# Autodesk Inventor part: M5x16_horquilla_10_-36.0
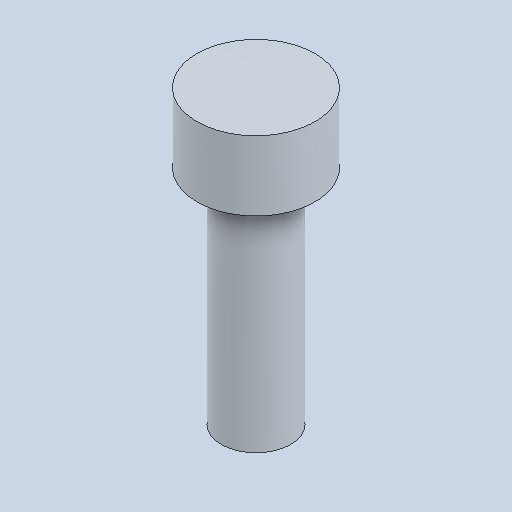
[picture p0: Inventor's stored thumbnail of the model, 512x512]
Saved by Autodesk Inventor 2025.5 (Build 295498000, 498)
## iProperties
Created: 2026-10
Part Number: M5x16_horquilla_10_-36.0
Material: Genérico
Document SubType Name: Modeling
Designer: Luis M
Density: 1 g/cm^3
Appearance: Valor por defecto
Author: Luis M
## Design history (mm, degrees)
feature "Base1"
node "Sólido1"
